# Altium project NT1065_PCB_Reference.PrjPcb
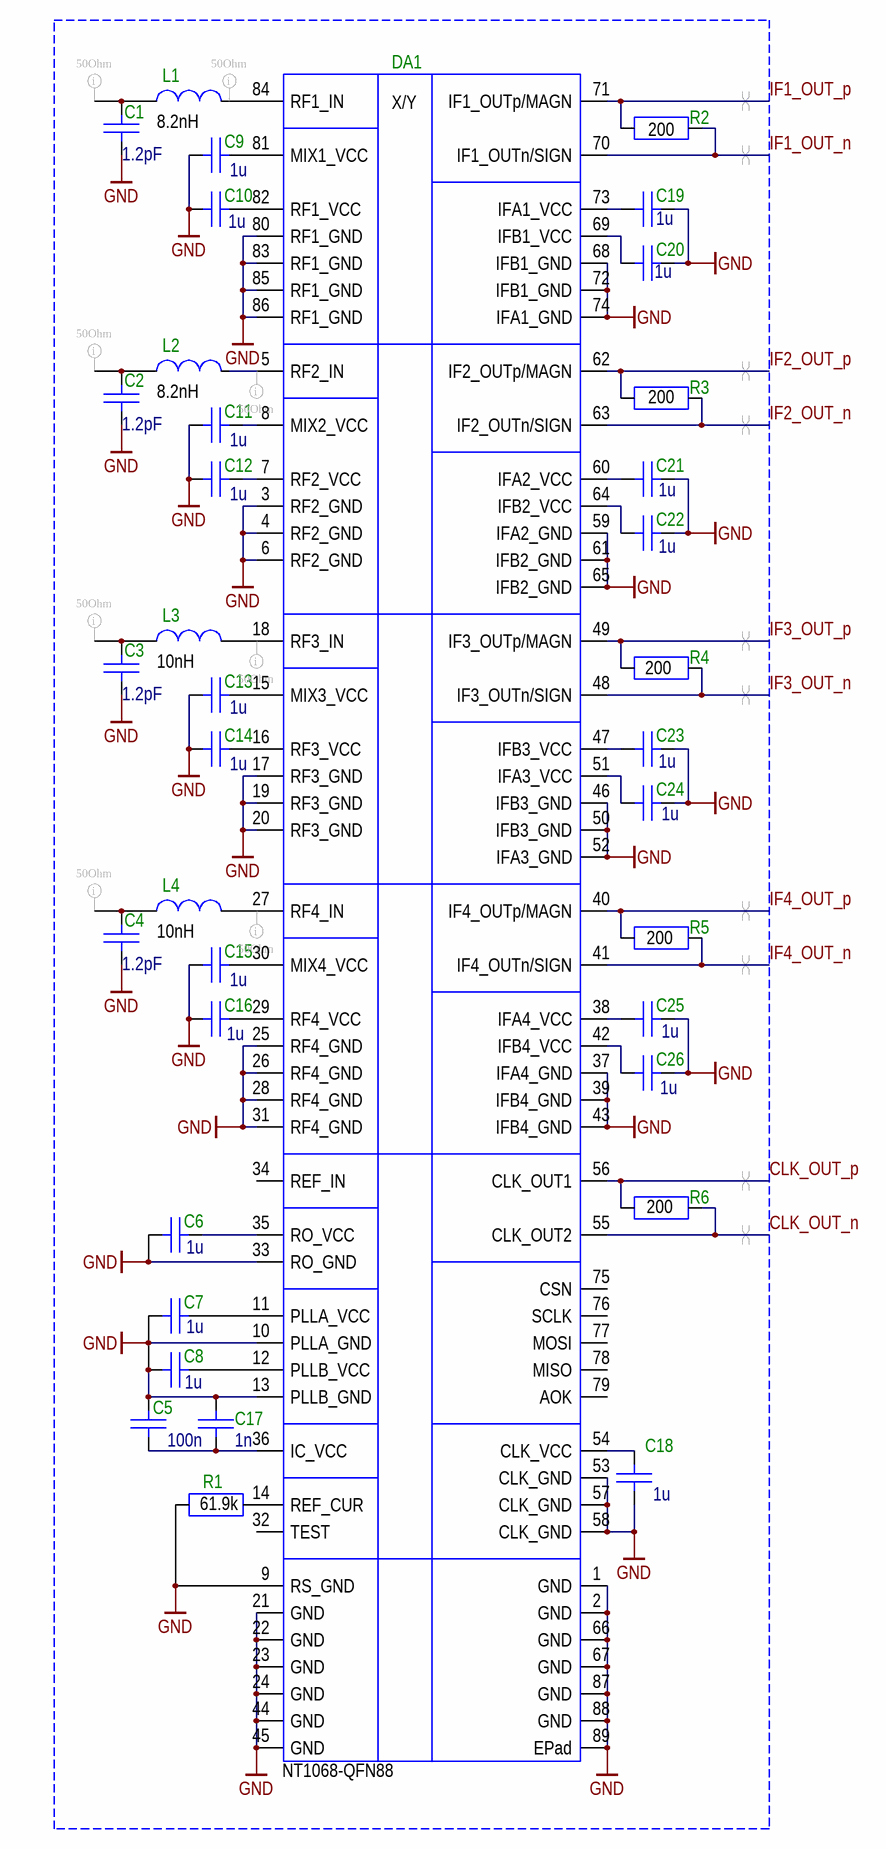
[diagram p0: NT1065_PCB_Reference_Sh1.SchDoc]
1 sheet, 37 parts. Net scope: global (net labels, ports and power ports of the same name join across sheets).
Board file: NT1065_PCB_Reference.PcbDoc

## Sheet NT1065_PCB_Reference_Sh1.SchDoc: Наименование
size 594 x 420 mm; CompanyName: NTLab; SheetTotal: 1; PageSetup: Record=PageOptions¦CenterHorizontal=True¦CenterVertical=True¦PrintScale=0.94¦XCorrection=1.00¦YCorrection=1.00¦PrintKind=1¦BorderSize=5000000¦LeftOffset=0¦BottomOffset=0¦Orientation=1¦PaperLength=1000¦PaperWidth=1000¦Scale=100¦PaperSource=7¦PrintQuality=-4¦MediaType=1¦DitherType=10¦PaperKind=A4¦PrintScaleMode=1; Перв.примен.: Перв.примен.; Тип изделия: Reference Design; Вид схемы: Схема электрическая принципиальная; Название изделия: NT1065

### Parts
C1  1.2pF  [0402_C]
C2  1.2pF  [0402_C]
C3  1.2pF  [0402_C]
C4  1.2pF  [0402_C]
C5  100n  [0402_C]
C6  1u  [0402_C]
C7  1u  [0402_C]
C8  1u  [0402_C]
C9  1u  [0402_C]
C10  1u  [0402_C]
C11  1u  [0402_C]
C12  1u  [0402_C]
C13  1u  [0402_C]
C14  1u  [0402_C]
C15  1u  [0402_C]
C16  1u  [0402_C]
C17  1n  [0402_C]
C18  1u  [0402_C]
C19  1u  [0402_C]
C20  1u  [0402_C]
C21  1u  [0402_C]
C22  1u  [0402_C]
C23  1u  [0402_C]
C24  1u  [0402_C]
C25  1u  [0402_C]
C26  1u  [0402_C]
DA1  NT1068-QFN88  [QFN-88_NT1065]
L1  8.2nH  [0402_L]
L2  8.2nH  [0402_L]
L3  10nH  [0402_L]
L4  10nH  [0402_L]
R1  61.9k  [0402_R]
R2  200  [0402_R]
R3  200  [0402_R]
R4  200  [0402_R]
R5  200  [0402_R]
R6  200  [0402_R]

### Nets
GND: C1.2 C2.2 C3.2 C4.2 C5.1 C6.2 C7.2 C8.2 C9.2 C10.2 C11.2 C12.2 C13.2 C14.2 C15.2 C16.2 C17.1 C18.2 C19.1 C20.1 C21.1 C22.1 C23.1 C24.1 C25.1 C26.1 DA1.1(GND) DA1.2(GND) DA1.3(RF2_GND) DA1.4(RF2_GND) DA1.6(RF2_GND) DA1.9(RS_GND) DA1.10(PLLA_GND) DA1.13(PLLB_GND) DA1.17(RF3_GND) DA1.19(RF3_GND) DA1.20(RF3_GND) DA1.21(GND) DA1.22(GND) DA1.23(GND) DA1.24(GND) DA1.25(RF4_GND) DA1.26(RF4_GND) DA1.28(RF4_GND) DA1.31(RF4_GND) DA1.33(RO_GND) DA1.37(IFA4_GND) DA1.39(IFB4_GND) DA1.43(IFB4_GND) DA1.44(GND) DA1.45(GND) DA1.46(IFB3_GND) DA1.50(IFB3_GND) DA1.52(IFA3_GND) DA1.53(CLK_GND) DA1.57(CLK_GND) DA1.58(CLK_GND) DA1.59(IFA2_GND) DA1.61(IFB2_GND) DA1.65(IFB2_GND) DA1.66(GND) DA1.67(GND) DA1.68(IFB1_GND) DA1.72(IFB1_GND) DA1.74(IFA1_GND) DA1.80(RF1_GND) DA1.83(RF1_GND) DA1.85(RF1_GND) DA1.86(RF1_GND) DA1.87(GND) DA1.88(GND) DA1.89(EPad) R1.1
CLK_OUT_n: DA1.55(CLK_OUT2) R6.2
CLK_OUT_p: DA1.56(CLK_OUT1) R6.1
IF1_OUT_n: DA1.70(IF1_OUTn/SIGN) R2.2
IF1_OUT_p: DA1.71(IF1_OUTp/MAGN) R2.1
IF2_OUT_n: DA1.63(IF2_OUTn/SIGN) R3.2
IF2_OUT_p: DA1.62(IF2_OUTp/MAGN) R3.1
IF3_OUT_n: DA1.48(IF3_OUTn/SIGN) R4.2
IF3_OUT_p: DA1.49(IF3_OUTp/MAGN) R4.1
IF4_OUT_n: DA1.41(IF4_OUTn/SIGN) R5.2
IF4_OUT_p: DA1.40(IF4_OUTp/MAGN) R5.1
NetC1_1: C1.1 L1.2
NetC2_1: C2.1 L2.2
NetC3_1: C3.1 L3.2
NetC4_1: C4.1 L4.2
NetC5_2: C5.2 C17.2 DA1.36(IC_VCC)
NetC6_1: C6.1 DA1.35(RO_VCC)
NetC7_1: C7.1 DA1.11(PLLA_VCC)
NetC8_1: C8.1 DA1.12(PLLB_VCC)
NetC9_1: C9.1 DA1.81(MIX1_VCC)
NetC10_1: C10.1 DA1.82(RF1_VCC)
NetC11_1: C11.1 DA1.8(MIX2_VCC)
NetC12_1: C12.1 DA1.7(RF2_VCC)
NetC13_1: C13.1 DA1.15(MIX3_VCC)
NetC14_1: C14.1 DA1.16(RF3_VCC)
NetC15_1: C15.1 DA1.30(MIX4_VCC)
NetC16_1: C16.1 DA1.29(RF4_VCC)
NetC18_1: C18.1 DA1.54(CLK_VCC)
NetC19_2: C19.2 DA1.73(IFA1_VCC)
NetC20_2: C20.2 DA1.69(IFB1_VCC)
NetC21_2: C21.2 DA1.60(IFA2_VCC)
NetC22_2: C22.2 DA1.64(IFB2_VCC)
NetC23_2: C23.2 DA1.47(IFB3_VCC)
NetC24_2: C24.2 DA1.51(IFA3_VCC)
NetC25_2: C25.2 DA1.38(IFA4_VCC)
NetC26_2: C26.2 DA1.42(IFB4_VCC)
NetDA1_5: DA1.5(RF2_IN) L2.1
NetDA1_14: DA1.14(REF_CUR) R1.2
NetDA1_18: DA1.18(RF3_IN) L3.1
NetDA1_27: DA1.27(RF4_IN) L4.1
NetDA1_84: DA1.84(RF1_IN) L1.1

Not connected (* = marked no-connect by the designer): DA1 32(TEST) 34(REF_IN) 75(CSN) 76(SCLK) 77(MOSI) 78(MISO) 79(AOK)

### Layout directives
net class 50Ohm: NetC1_1, NetC2_1, NetC3_1, NetC4_1, NetDA1_5, NetDA1_18, NetDA1_27, NetDA1_84
differential pair; differential pair class 100Ohm_Diff: CLK_OUT_n, CLK_OUT_p
differential pair; differential pair class 200Ohm_Diff: IF1_OUT_n, IF1_OUT_p, IF2_OUT_n, IF2_OUT_p, IF3_OUT_n, IF3_OUT_p, IF4_OUT_n, IF4_OUT_p

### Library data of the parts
C1-C4 = C 1.2: 1.2pF, +-0.25pF, 50V, 0402, COG; PART_NUMBER: 0402N1R2C500N; PART_NAME: Hitano; Part_Label: 1.2пФ, +-0.25пФ, 50В, 0402, COG; Value: 1.2p
C5 = C 104: 0.1uF, 10%, 16V, 0402, X7R; PART_NUMBER: GRM155R71C104KA88D; PART_NAME: Murata; Part_Label: 0.1мкФ, 10%, 16В, 0402, X7R
C6-C16 C18-C26 = C 105: 1uF 10%, 10V, 0402, X5R; PART_NUMBER: GRM155R61A105K; PART_NAME: Murata; Part_Label: 1мкФ, 10%, 10В, 0402, X5R
C17 = C 102: 1nF, 5%, 25V, 0402, C0G; PART_NUMBER: GRM1555C1H102JA01D; PART_NAME: KEMET; Part_Label: 1нФ, 5%, 25В, 0402, C0G
DA1 = DA NT1065: RF Front-End, ADC, QFN88; Part_Label: IC, RF Front-End, ADC, QFN88; PART_NAME: NTL; IntHelpURL: \\dd\RF_departament\Datasheets\NT1065\NT1065.2\Datasheet\NT1065.2\SE\NT1065 SE DS v2.08.pdf
L1 L2 = L8.2_1: 8.2nH, 2%, 0.54A, 0402; PART_NUMBER: LQW15AN8N2G00; Part_Label: 8.2нГ, 2%, 0.54А, 0402; PART_NAME: Murata; Part Number: L3.6; Всего приобретено: 100 шт.
L3 L4 = L100: 10 nH, 2%, 0.54A, 0402; PART_NUMBER: LQW15AN10NG00; Part_Label: 10нГ, 2%, 0.54А, 0402; PART_NAME: Murata; Part Number: L3.6; Всего приобретено: 100 шт.
R1 = R 6192: 61.9 kOhm, 1%, 0402; PART_NUMBER: RC0402FR-0761K9L; PART_NAME: FaithfulLink; Part_Label: 61.9 кОм, 1%, 0402
R2-R6 = R201: 200 Ohm, 5%, 0402; PART_NAME: FaithfulLink; PART_NUMBER: RC0402J200R; Part_Label: 200 Ом, 5%, 0402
